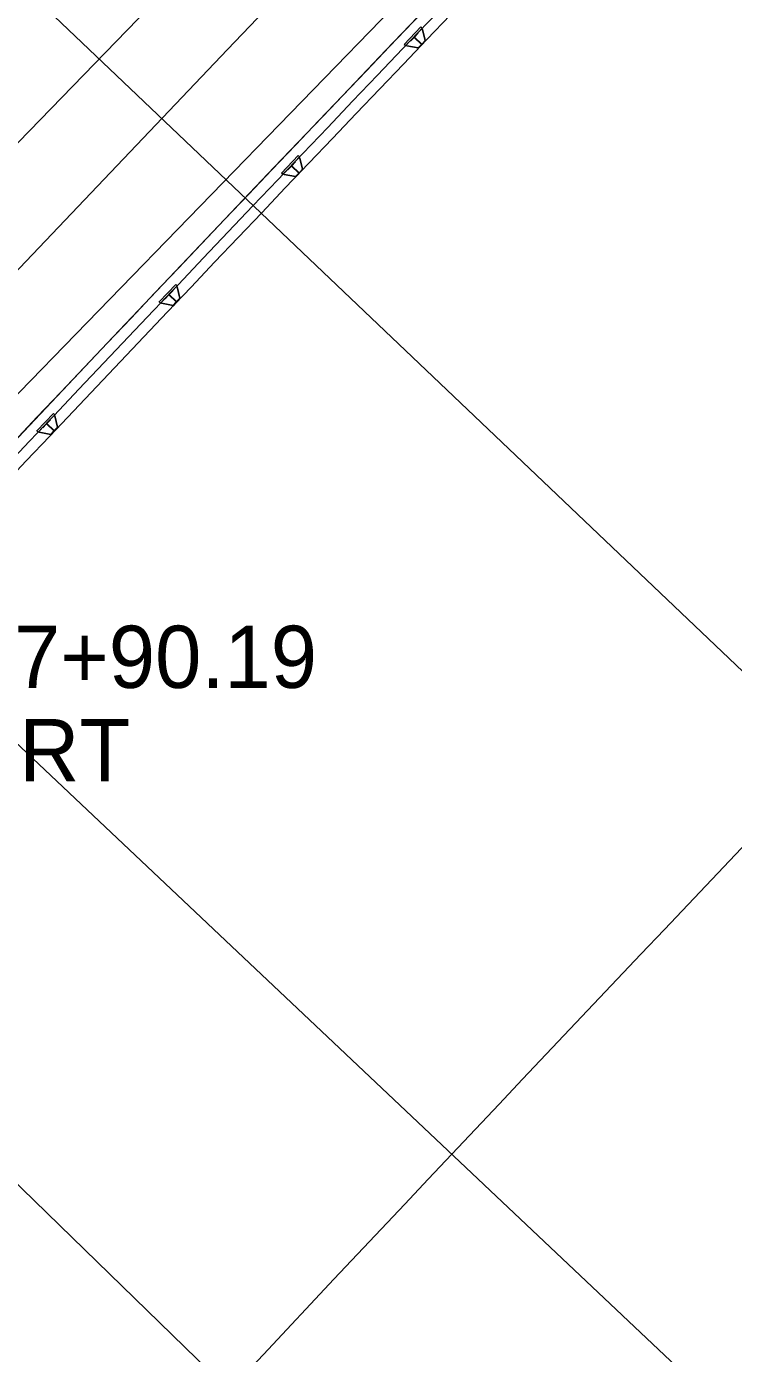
# Model space of a CAD drawing. Extents: x 2376379 to 2383101, y 559608 to 561720.
# Drawn here: x 2377030.1 to 2377061.9, y 561165 to 561224.7 of the extents above; entities that cross this region are included whole.
import ezdxf

# ---------------------------------------------------------------- set-up
doc = ezdxf.new("R2010")
doc.units = 0
for name, color, linetype in [('BR_X_SV_Bottom_of_Beam', 7, 'Continuous'), ('DT_X_Contour_Minor', 7, 'Continuous'), ('HY_X_Water_Edge', 7, 'Continuous'), ('PM_X_CL_Dashed', 7, 'Continuous'), ('PM_X_CL_Pass_Proh_Lt', 7, 'Continuous'), ('PM_X_Edge_Line', 7, 'Continuous'), ('PM_X_Surveyed_Line', 7, 'Continuous'), ('PV_X_COP', 7, 'Continuous'), ('PV_X_Shoulder', 7, 'Continuous'), ('RD_X_Cells', 7, 'Continuous'), ('RD_X_GR_Lt', 7, 'Continuous'), ('SV_X_Control_Cells_Found', 7, 'Continuous'), ('UT_X_Gas_Cells', 7, 'Continuous')]:
    doc.layers.add(name, color=color, linetype=linetype)

msp = doc.modelspace()

# ---------------------------------------------------------------- linework, layer by layer
at = {"layer": 'BR_X_SV_Bottom_of_Beam'}
for radius in [5724.68, 5713.68]:
    msp.add_arc((2381174.86, 557281.309), radius, 134.056462, 138.414594, dxfattribs=at)
at = {"layer": 'DT_X_Contour_Minor'}
msp.add_arc((2381174.86, 557281.309), 5672.16, 134.914809, 136.914686, dxfattribs=at)
at = {"layer": 'HY_X_Water_Edge'}
msp.add_line((2376918.197, 561280.86), (2377079.942, 561123.72), dxfattribs=at)
at = {"layer": 'PM_X_CL_Dashed'}
for p, q in [((2377047.683, 561224.365), (2377047.338, 561224.004)), ((2377047.699, 561224.35), (2377047.533, 561224.177)), ((2377047.683, 561224.365), (2377047.885, 561224.577)), ((2377047.683, 561224.365), (2377047.699, 561224.35)), ((2377047.885, 561224.577), (2377047.825, 561224.634)), ((2377047.893, 561224.525), (2377047.863, 561224.553)), ((2377047.893, 561224.525), (2377048.012, 561224.019)), ((2377047.137, 561223.793), (2377047.076, 561223.851)), ((2377047.137, 561223.793), (2377047.338, 561224.004)), ((2377047.189, 561223.788), (2377047.159, 561223.816)), ((2377047.189, 561223.788), (2377047.7, 561223.692)), ((2377047.338, 561224.004), (2377047.354, 561223.99)), ((2377047.52, 561224.163), (2377047.354, 561223.99)), ((2377047.52, 561224.163), (2377047.849, 561223.848)), ((2377047.533, 561224.177), (2377047.863, 561223.862)), ((2377047.849, 561223.848), (2377047.684, 561223.675)), ((2377048.044, 561224.021), (2377047.699, 561223.66)), ((2377048.028, 561224.036), (2377047.863, 561223.862)), ((2377048.028, 561224.036), (2377048.044, 561224.021)), ((2377047.684, 561223.675), (2377047.699, 561223.66)), ((2377042.161, 561218.578), (2377041.817, 561218.216)), ((2377041.998, 561218.375), (2377041.833, 561218.201)), ((2377041.998, 561218.375), (2377042.328, 561218.061)), ((2377042.177, 561218.563), (2377042.011, 561218.389)), ((2377042.011, 561218.389), (2377042.342, 561218.075)), ((2377042.161, 561218.578), (2377042.363, 561218.789)), ((2377042.161, 561218.578), (2377042.177, 561218.563)), ((2377042.363, 561218.789), (2377042.302, 561218.847)), ((2377042.371, 561218.737), (2377042.341, 561218.766)), ((2377042.371, 561218.737), (2377042.491, 561218.231)), ((2377041.616, 561218.005), (2377041.555, 561218.062)), ((2377041.616, 561218.005), (2377041.817, 561218.216)), ((2377041.668, 561217.999), (2377041.638, 561218.028)), ((2377041.668, 561217.999), (2377042.179, 561217.904)), ((2377041.817, 561218.216), (2377041.833, 561218.201)), ((2377042.328, 561218.061), (2377042.163, 561217.887)), ((2377042.163, 561217.887), (2377042.178, 561217.872)), ((2377042.523, 561218.233), (2377042.178, 561217.872)), ((2377042.507, 561218.248), (2377042.342, 561218.075)), ((2377042.507, 561218.248), (2377042.523, 561218.233)), ((2377036.648, 561212.782), (2377036.849, 561212.994)), ((2377036.849, 561212.994), (2377036.788, 561213.051)), ((2377036.103, 561212.208), (2377036.304, 561212.42)), ((2377036.648, 561212.782), (2377036.304, 561212.42)), ((2377036.304, 561212.42), (2377036.32, 561212.405)), ((2377036.485, 561212.579), (2377036.32, 561212.405)), ((2377036.485, 561212.579), (2377036.815, 561212.265)), ((2377036.663, 561212.767), (2377036.498, 561212.593)), ((2377036.498, 561212.593), (2377036.829, 561212.279)), ((2377036.648, 561212.782), (2377036.663, 561212.767)), ((2377037.01, 561212.438), (2377036.666, 561212.076)), ((2377036.857, 561212.942), (2377036.827, 561212.971)), ((2377036.994, 561212.453), (2377036.829, 561212.279)), ((2377036.857, 561212.942), (2377036.978, 561212.436)), ((2377036.994, 561212.453), (2377037.01, 561212.438)), ((2377036.103, 561212.208), (2377036.042, 561212.266)), ((2377036.155, 561212.203), (2377036.125, 561212.232)), ((2377036.155, 561212.203), (2377036.666, 561212.108)), ((2377036.815, 561212.265), (2377036.65, 561212.091)), ((2377036.65, 561212.091), (2377036.666, 561212.076)), ((2377031.142, 561206.979), (2377031.343, 561207.191)), ((2377031.343, 561207.191), (2377031.282, 561207.248)), ((2377031.351, 561207.139), (2377031.321, 561207.168)), ((2377031.351, 561207.139), (2377031.472, 561206.633)), ((2377030.598, 561206.404), (2377030.537, 561206.462)), ((2377030.598, 561206.404), (2377030.799, 561206.617)), ((2377030.65, 561206.399), (2377030.62, 561206.428)), ((2377031.142, 561206.979), (2377030.799, 561206.617)), ((2377030.799, 561206.617), (2377030.814, 561206.602)), ((2377030.98, 561206.776), (2377030.814, 561206.602)), ((2377030.98, 561206.776), (2377031.31, 561206.462)), ((2377031.158, 561206.964), (2377030.993, 561206.79)), ((2377030.993, 561206.79), (2377031.324, 561206.476)), ((2377031.142, 561206.979), (2377031.158, 561206.964)), ((2377031.31, 561206.462), (2377031.145, 561206.288)), ((2377031.504, 561206.636), (2377031.161, 561206.273)), ((2377031.489, 561206.651), (2377031.324, 561206.476)), ((2377031.489, 561206.651), (2377031.504, 561206.636)), ((2377030.65, 561206.399), (2377031.162, 561206.305)), ((2377031.145, 561206.288), (2377031.161, 561206.273))]:
    msp.add_line(p, q, dxfattribs=at)
for points in [[(2377047.076, 561223.851), (2377047.076, 561223.851), (2377047.825, 561224.634)], [(2377041.555, 561218.062), (2377041.555, 561218.062), (2377042.302, 561218.847)], [(2377036.042, 561212.266), (2377036.042, 561212.266), (2377036.788, 561213.051)], [(2377030.537, 561206.462), (2377030.537, 561206.462), (2377031.282, 561207.248)]]:
    msp.add_lwpolyline(points, dxfattribs=at)
for radius, start, end in [(5708.502, 134.056462, 138.734789), (5708.002, 134.783851, 136.871541)]:
    msp.add_arc((2381174.86, 557281.309), radius, start, end, dxfattribs=at)
at = {"layer": 'PM_X_CL_Pass_Proh_Lt'}
for centre, radius, start, end in [((2381174.86, 557281.309), 5750.502, 134.4393655, 138.0925584), ((2381174.917, 557281.256), 5751.08, 134.7915077, 136.8639244)]:
    msp.add_arc(centre, radius, start, end, dxfattribs=at)
at = {"layer": 'PM_X_Edge_Line'}
for centre, radius, start, end in [((2381174.86, 557281.309), 5728.92, 134.539622, 137.114945), ((2381174.917, 557281.256), 5750.58, 134.8496279, 136.8055852), ((2381174.917, 557281.256), 5708.58, 134.842434, 136.812784)]:
    msp.add_arc(centre, radius, start, end, dxfattribs=at)
at = {"layer": 'PM_X_Surveyed_Line'}
for p, q in [((2376937.47, 561314.447), (2377111.313, 561148.983)), ((2377094.477, 561131.217), (2376919.913, 561295.921))]:
    msp.add_line(p, q, dxfattribs=at)
at = {"layer": 'PV_X_COP'}
for radius in [5745.18, 5734.18]:
    msp.add_arc((2381174.86, 557281.309), radius, 134.0564619, 138.4145938, dxfattribs=at)
at = {"layer": 'PV_X_Shoulder'}
msp.add_arc((2381174.917, 557281.256), 5729.58, 134.8522952, 136.8022952, dxfattribs=at)
at = {"layer": 'RD_X_Cells'}
msp.add_arc((2381174.86, 557281.309), 5729.93, 134.0564619, 139.4731285, dxfattribs=at)
msp.add_arc((2381174.86, 557281.309), 5729.93, 134.0564619, 139.4731285, dxfattribs=at)
at = {"layer": 'SV_X_Control_Cells_Found'}
for radius, start, end in [(5751.58, 134.8460617, 136.8085286), (5707.58, 134.838497, 136.816094)]:
    msp.add_arc((2381174.917, 557281.256), radius, start, end, dxfattribs=at)
at = {"layer": 'UT_X_Gas_Cells'}
for p, q in [((2377142.124, 561335.17), (2377006.25, 561195.315)), ((2377147.772, 561329.683), (2377011.898, 561189.827))]:
    msp.add_line(p, q, dxfattribs=at)

# ---------------------------------------------------------------- texts
at = {"layer": 'RD_X_GR_Lt'}
for s, p in [('2787+90.19', (2377023.262, 561194.898)), ('05°25\'00" RT', (2377012.672, 561190.698))]:
    msp.add_text(s, height=2.8, dxfattribs=at).set_placement(p)

doc.saveas('drawing.dxf')
